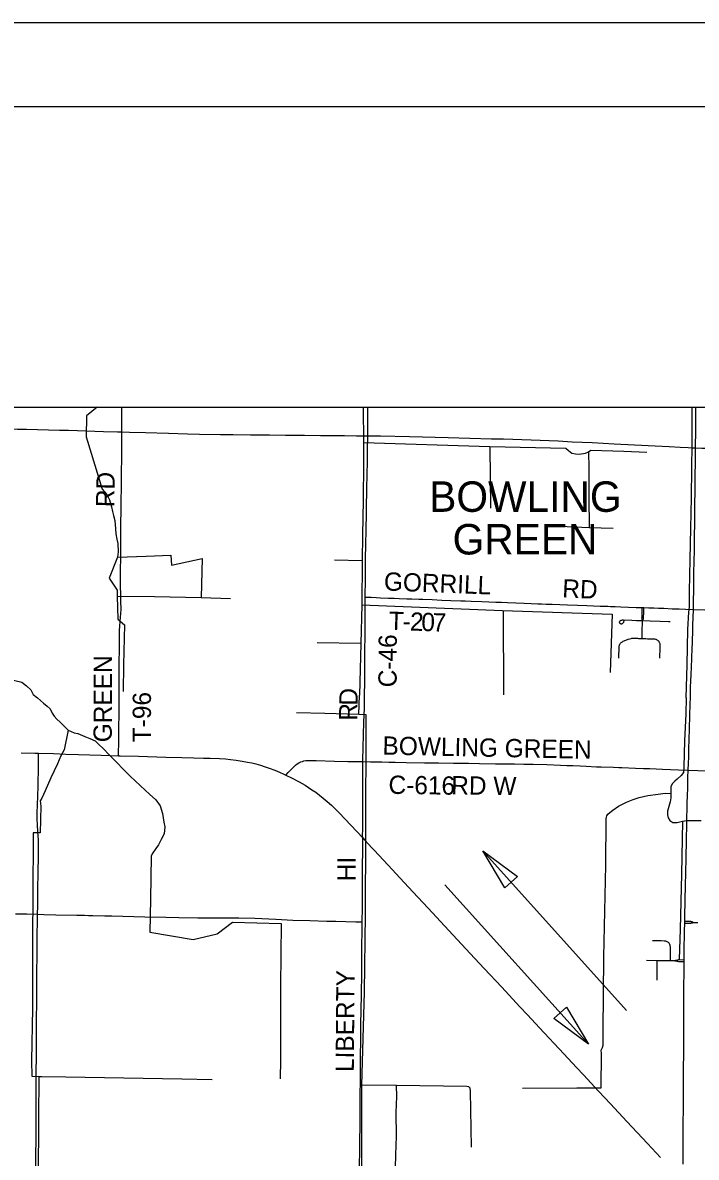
# Model space of a CAD drawing. Extents: x 0 to 680, y 0 to 834.
# Drawn here: x 187.9 to 268.3, y 304.5 to 440 of the extents above; entities that cross this region are included whole.
import ezdxf

# ---------------------------------------------------------------- set-up
doc = ezdxf.new("R2010")
doc.units = 0
for name, color, linetype in [('GM_X_City_Street', 7, 'Continuous'), ('GM_X_Corporation_Text', 7, 'Continuous'), ('GM_X_County_Road', 7, 'Continuous'), ('GM_X_County_Road_Text', 7, 'Continuous'), ('GM_X_Interstate_Route', 7, 'Continuous'), ('GM_X_Minor_River', 7, 'Continuous'), ('GM_X_Township_Road', 7, 'Continuous'), ('GM_X_Township_Road_Text', 7, 'Continuous'), ('GM_X_US_Route', 7, 'Continuous'), ('SH_Border', 7, 'Continuous'), ('SH_Cut_Line', 7, 'Continuous'), ('SH_Text', 7, 'Continuous')]:
    doc.layers.add(name, color=color, linetype=linetype)

msp = doc.modelspace()

# ---------------------------------------------------------------- linework, layer by layer
at = {"layer": 'GM_X_City_Street'}
for points in [[(261.93, 368.6), (261.87, 368.78), (261.86, 368.83), (261.85, 368.91), (261.86, 369.03), (261.86, 369.27), (261.89, 370.11), (261.9, 370.16)], [(261.93, 368.6), (262, 368.75), (262.03, 368.84), (262.05, 368.94), (262.05, 369.15), (262.06, 369.42), (262.08, 370.15)], [(259.73, 368.66), (259.69, 368.53), (259.65, 368.44), (259.63, 368.38), (259.6, 368.33), (259.57, 368.29), (259.54, 368.25), (259.5, 368.22), (259.46, 368.2), (259.41, 368.19), (259.37, 368.19), (259.32, 368.2), (259.28, 368.22), (259.24, 368.25), (259.21, 368.29), (259.19, 368.33), (259.17, 368.38), (259.17, 368.42), (259.18, 368.47), (259.19, 368.52), (259.23, 368.57), (259.27, 368.61), (259.31, 368.63), (259.35, 368.65), (259.4, 368.66), (259.45, 368.67), (259.52, 368.68), (259.64, 368.68), (260.64, 368.65), (261.21, 368.63), (261.83, 368.61), (261.93, 368.6), (262.83, 368.58), (264.02, 368.53), (265, 368.5), (265.21, 368.5)], [(261.85, 366.47), (261.86, 366.5), (261.88, 367.24), (261.93, 368.57), (261.93, 368.6)], [(259.07, 364.11), (259.07, 364.13), (259.09, 364.47), (259.11, 365.14), (259.11, 365.38), (259.12, 365.52), (259.14, 365.59), (259.16, 365.68), (259.2, 365.77), (259.23, 365.83), (259.27, 365.89), (259.32, 365.94), (259.37, 365.99), (259.43, 366.03), (259.51, 366.08), (259.6, 366.13), (259.73, 366.18), (260.22, 366.37), (260.4, 366.44), (260.54, 366.48), (260.64, 366.49), (260.77, 366.5), (260.89, 366.5), (261.32, 366.49), (261.42, 366.48), (261.85, 366.47), (262.09, 366.46), (262.13, 366.46), (262.23, 366.46), (262.3, 366.45), (262.49, 366.44), (263.02, 366.43), (263.23, 366.42), (263.35, 366.41), (263.45, 366.39), (263.51, 366.37), (263.58, 366.34), (263.64, 366.31), (263.7, 366.27), (263.76, 366.22), (263.81, 366.17), (263.85, 366.12), (263.89, 366.06), (263.92, 365.99), (263.95, 365.93), (263.97, 365.86), (263.98, 365.76), (263.99, 365.67), (263.99, 365.52), (263.98, 365.19), (263.95, 364.33), (263.94, 364.12)], [(266.96, 332.71), (267.09, 332.71), (267.57, 332.7), (267.64, 332.7), (267.72, 332.69), (267.79, 332.67), (267.87, 332.62), (267.93, 332.57)], [(266.96, 332.48), (267.08, 332.48), (267.57, 332.48), (267.67, 332.49), (267.74, 332.5), (267.8, 332.51), (267.87, 332.53), (267.93, 332.57)], [(267.93, 332.57), (268.02, 332.57), (268.5, 332.57)], [(265.26, 328.02), (265.26, 328.23), (265.25, 328.97), (265.26, 329.28), (265.25, 329.5), (265.25, 329.63), (265.23, 329.74), (265.22, 329.81), (265.18, 329.92), (265.14, 330.01), (265.08, 330.08), (265.01, 330.15), (264.94, 330.21), (264.86, 330.26), (264.79, 330.29), (264.71, 330.32), (264.65, 330.33), (264.58, 330.34), (264.49, 330.34), (264.15, 330.35), (263.1, 330.35)], [(262.4, 328.04), (263.65, 328.03), (263.96, 328.03), (265.26, 328.02), (265.3, 328.02), (265.54, 328.02)], [(263.65, 325.66), (263.65, 326.52), (263.65, 327.18), (263.65, 327.84), (263.65, 328.03)], [(265.54, 328.02), (266.14, 328.11), (266.23, 328.12), (266.29, 328.12), (266.86, 328.11), (266.89, 328.11)], [(265.54, 328.02), (265.99, 327.94), (266.13, 327.92), (266.21, 327.91), (266.28, 327.91), (266.52, 327.9), (266.86, 327.9), (266.88, 327.9)]]:
    msp.add_lwpolyline(points, dxfattribs=at)
at = {"layer": 'GM_X_County_Road'}
for points in [[(229.12, 390.4), (229.12, 390.66), (229.12, 393.31), (229.13, 394.07)], [(171.09, 391.7), (172.88, 391.68), (176.1, 391.64), (179.68, 391.58), (181.59, 391.55), (183.26, 391.53), (184.21, 391.51), (187.31, 391.45), (188.39, 391.45), (192.33, 391.36), (193.4, 391.33), (194.47, 391.3), (197.57, 391.2), (199.25, 391.15), (199.76, 391.14)], [(199.76, 391.14), (200.68, 391.11), (202.59, 391.06), (205.33, 390.97), (207.59, 390.91), (209.03, 390.88), (211.53, 390.83), (213.05, 390.81), (215.11, 390.78), (217.38, 390.77), (219.29, 390.75), (220.48, 390.74), (221.56, 390.73), (223.46, 390.72), (224.54, 390.71), (226.33, 390.69), (227.76, 390.67), (228.59, 390.65), (229.12, 390.66)], [(228.81, 371.15), (228.81, 371.41), (228.84, 373.54), (228.86, 375.45), (228.9, 378.2), (228.91, 378.91), (228.96, 381.89), (229.01, 384.4), (229.07, 387.62), (229.09, 389.41), (229.11, 390.36), (229.12, 390.4)], [(229.12, 390.66), (229.19, 390.66), (229.67, 390.67), (230.62, 390.66), (234.08, 390.58), (238.73, 390.45), (243.87, 390.32), (245.3, 390.29), (248.64, 390.19), (251.86, 390.06), (253.53, 389.96), (255.91, 389.85), (258.53, 389.71)], [(258.53, 389.71), (262.59, 389.52), (265.09, 389.38), (266.4, 389.31), (267.35, 389.27), (267.77, 389.25), (268.25, 389.23)], [(268.25, 389.23), (269.01, 389.21), (269.85, 389.2), (271.64, 389.18), (273.43, 389.14), (276.17, 389.09), (279.63, 389.03), (281.88, 388.98)], [(228.74, 359.83), (228.75, 361.14), (228.75, 362.69), (228.77, 363.76), (228.77, 364.83), (228.79, 366.98), (228.79, 367.7), (228.79, 368.17), (228.8, 370.08), (228.81, 371.15)], [(228.54, 351.48), (228.54, 351.76), (228.54, 351.95), (228.66, 356.48), (228.73, 358.15), (228.73, 358.75), (228.74, 359.83)], [(219.33, 350.16), (219.6, 350.46), (219.98, 350.84), (220.28, 351.13), (220.5, 351.33), (220.69, 351.48), (220.88, 351.61), (220.98, 351.66), (221.14, 351.74), (221.31, 351.79), (221.48, 351.84), (221.71, 351.88), (221.89, 351.9), (222.18, 351.91), (222.96, 351.9), (225.16, 351.83), (226.72, 351.79), (228.27, 351.76), (228.54, 351.76)], [(228.53, 342.37), (228.53, 342.41), (228.52, 342.66), (228.5, 343), (228.51, 343.6), (228.52, 345.75), (228.53, 347.54), (228.54, 350.28), (228.54, 351.48)], [(228.54, 351.76), (229.46, 351.74), (230.81, 351.72), (231.63, 351.7), (232.38, 351.68), (233.7, 351.66), (235.9, 351.62), (237.58, 351.6), (239.37, 351.58), (241.16, 351.57), (242.47, 351.55), (244.38, 351.51), (245.81, 351.49), (246.64, 351.49), (247.75, 351.47), (248.87, 351.45), (250.51, 351.4), (252.13, 351.34)], [(252.13, 351.34), (252.87, 351.31), (253.58, 351.28), (254.47, 351.24), (255.19, 351.21), (256.44, 351.16), (256.87, 351.15), (256.96, 351.15)], [(256.96, 351.15), (258.44, 351.09), (259.1, 351.06), (259.46, 351.05), (261.07, 350.99), (262.03, 350.96), (262.78, 350.93), (264.31, 350.87), (266.21, 350.79), (267.36, 350.75)], [(267.36, 350.75), (269.66, 350.65), (269.83, 350.64), (271.33, 350.59), (273.6, 350.49), (275.21, 350.43), (276.94, 350.36), (277.07, 350.35)], [(228.45, 332.36), (228.45, 332.63), (228.46, 332.98), (228.48, 333.94), (228.47, 334.65), (228.48, 335.37), (228.49, 337.04), (228.5, 339.43), (228.51, 340.98), (228.53, 341.93), (228.53, 342.37)], [(228.18, 298.27), (228.17, 298.53), (228.17, 298.79), (228.15, 299.46), (228.14, 300.18), (228.13, 301.37), (228.15, 303.16), (228.19, 305.66), (228.22, 309.12), (228.23, 310.91), (228.25, 314.73), (228.31, 320.34), (228.35, 323.92), (228.39, 326.54), (228.42, 328.93), (228.45, 332.36)]]:
    msp.add_lwpolyline(points, dxfattribs=at)
at = {"layer": 'GM_X_Interstate_Route'}
msp.add_lwpolyline([(44.69, 394.07), (374.69, 394.07), (374.69, 64.07), (44.69, 64.07)], close=True, dxfattribs=at)
at = {"layer": 'GM_X_Minor_River'}
for points in [[(196.82, 394.07), (195.56, 393.06), (195.49, 390.53), (197.43, 384.31), (197.99, 383.68), (198.27, 383.04), (198.51, 382.17), (198.63, 381.63), (198.77, 381.14), (198.92, 380.56), (199, 379.58), (199.05, 378.96), (199.15, 378.32), (199.27, 377.79), (199.34, 376.83), (199.26, 376.17), (198.25, 373.65), (199.2, 372.23), (199.2, 371.53), (199.28, 368.77), (200.08, 368.11), (199.97, 363.31), (199.93, 360.15)], [(228.58, 394.07), (228.61, 389.87), (228.61, 387.39), (228.57, 382.94), (228.49, 378.86), (228.46, 375.73), (228.4, 370.47), (228.28, 365.86), (228.14, 359.71)], [(267.14, 359.37), (267.25, 363.31), (267.34, 367.55), (267.43, 369.59), (267.53, 370.22), (267.53, 372.09), (267.6, 375.9), (267.69, 379.66), (267.77, 383.29), (267.81, 386.79), (267.82, 389.58), (267.84, 393.6), (267.85, 394.07)], [(228.61, 389.87), (243.68, 389.4), (252.76, 389.18), (253.06, 388.9), (253.47, 388.61), (253.92, 388.5), (254.37, 388.46), (255.1, 388.58), (255.47, 388.76), (255.73, 388.96), (259.69, 388.83), (262.41, 388.71)], [(243.68, 389.4), (243.76, 382.02)], [(255.47, 388.76), (255.5, 386.75), (255.51, 383.33), (255.56, 379.73)], [(251.15, 379.9), (255.56, 379.73), (258.42, 379.66)], [(199.26, 376.17), (202.67, 376.31), (205.61, 376.43), (205.71, 375.22), (209.34, 376.03), (209.22, 371.36)], [(228.46, 375.73), (225.15, 375.82)], [(199.2, 371.53), (203.66, 371.49), (209.22, 371.36), (212.73, 371.26)], [(228.4, 370.47), (245.21, 369.82), (258.3, 369.39), (258.05, 362.39)], [(245.26, 369.79), (245.3, 359.75)], [(228.28, 365.86), (223.07, 365.93)], [(182.64, 360.38), (183.96, 360.9), (184.92, 361.23), (185.72, 361.42), (186.28, 361.51), (186.99, 361.44), (187.81, 361.24), (188.4, 360.83), (188.89, 360.32)], [(188.89, 360.32), (189.16, 359.78), (189.7, 359.38), (190.4, 358.75), (190.86, 358.37), (191.22, 358.05), (191.46, 357.55), (191.67, 357.19), (192.02, 356.82), (192.39, 356.49), (193, 355.86), (193.37, 355.53), (194.07, 355.2), (194.51, 355.12), (195.35, 354.77), (195.95, 354.51), (196.56, 354.23), (197.07, 353.77), (197.49, 353.35), (198.33, 352.51), (200.77, 350.03), (202.53, 348.36), (203.05, 347.89), (203.84, 347.19), (204.32, 346.49), (204.61, 345.55), (204.79, 344.52), (204.89, 343.98), (204.8, 343.13), (204.47, 342.46), (204.14, 341.82), (203.84, 341.4), (203.4, 340.77), (203.26, 340.48), (203.18, 335.34), (203.12, 331.39), (208.26, 330.52), (211.13, 331.19), (212.97, 332.6), (218.79, 332.45), (218.72, 324.96), (218.71, 316.16), (218.66, 313.88)], [(228.06, 357.4), (228.14, 359.71)], [(267.14, 359.37), (267.07, 357.48), (266.92, 354.25), (266.86, 351.13), (266.82, 350.46), (266.53, 350.1), (266.03, 349.65), (265.78, 349.43), (265.46, 349.11), (265.3, 348.76), (265.28, 348.41), (265.31, 347.96), (265.29, 347.43), (265.21, 346.98), (265.07, 346.41), (264.91, 345.83), (264.9, 345.42), (264.97, 345.07), (265.18, 344.73), (265.52, 344.51), (266.06, 344.48), (266.7, 344.64), (267.17, 344.73), (267.97, 344.75), (268.93, 344.73)], [(228.96, 299.35), (228.86, 300.64), (228.73, 301.09), (228.6, 301.34), (228.46, 301.73), (228.42, 302.53), (228.42, 313.14), (228.74, 324.28), (228.83, 333.5), (228.87, 343.1), (228.89, 347.61), (228.91, 352.15), (228.94, 355.48), (228.93, 357.36), (228.06, 357.4), (223.98, 357.49), (220.6, 357.57)], [(193.37, 355.53), (192.89, 353.17), (192.49, 352.47), (192.08, 351.48), (191.27, 349.84), (190.63, 348.29), (190.2, 347.39), (190.01, 347.08), (190.11, 346.44), (190.01, 343.27), (189.18, 343.26), (189.12, 335.47), (189.09, 331.1), (189.09, 326.75), (189.09, 322.33), (188.99, 316.03), (189.01, 314.2), (189.84, 314.17), (190.2, 314.15), (193.06, 314.12), (200.02, 314), (206.93, 313.89), (210.54, 313.79)], [(247.59, 312.76), (254.07, 312.82), (256.96, 312.82), (257, 316.89), (256.99, 317.3), (257.13, 317.61), (257.22, 317.9), (257.2, 319.61), (257.31, 328.4), (257.53, 339.39), (257.59, 344.92), (257.61, 345.12), (257.67, 345.28), (257.76, 345.47), (258, 345.7), (258.36, 345.98), (259.04, 346.44), (260, 346.94), (260.78, 347.25), (261.51, 347.46), (262.53, 347.73), (263.77, 347.87), (264.63, 348), (265.31, 347.96)], [(266.7, 344.64), (266.55, 338.34), (266.41, 331.74), (266.3, 328.13)], [(189.84, 314.17), (189.8, 309.14), (189.79, 302.09), (189.81, 295.76), (189.8, 292.27)], [(241.51, 305.71), (241.37, 312.4), (241.34, 312.78), (241.18, 312.93), (240.95, 312.96), (232.56, 313.07), (228.42, 313.14)], [(232.41, 303.27), (232.47, 304.8), (232.54, 307.03), (232.5, 309.87), (232.58, 311.77), (232.56, 313.07)]]:
    msp.add_lwpolyline(points, dxfattribs=at)
at = {"layer": 'GM_X_Township_Road'}
for points in [[(199.76, 391.14), (199.76, 391.71), (199.77, 393.86), (199.77, 394.07)], [(268.25, 389.23), (268.25, 389.83), (268.26, 390.74), (268.27, 392.27), (268.29, 393.72), (268.29, 394.07)], [(199.46, 362.35), (199.46, 363.43), (199.47, 365.34), (199.49, 367.37), (199.51, 367.97), (199.55, 368.44), (199.62, 369.04), (199.65, 369.39), (199.67, 369.99), (199.66, 370.83), (199.63, 371.78), (199.6, 372.62), (199.59, 373.45), (199.6, 374.53), (199.63, 376.2), (199.65, 378.11), (199.65, 379.54), (199.66, 380.26), (199.67, 381.69), (199.7, 383), (199.72, 384.43), (199.74, 386.46), (199.76, 387.89), (199.75, 388.61), (199.76, 389.92), (199.77, 390.99), (199.76, 391.14)], [(267.98, 369.91), (267.99, 370.74), (268.02, 372.43), (268.04, 373.63), (268.05, 374.34), (268.07, 375.63), (268.1, 377.06), (268.13, 379.12), (268.14, 379.81), (268.15, 381.1), (268.16, 381.91), (268.17, 382.48), (268.17, 382.89), (268.18, 383.65), (268.18, 384.25), (268.19, 384.89), (268.21, 386.18), (268.22, 387.23), (268.23, 388), (268.24, 388.47), (268.25, 389.23)], [(228.81, 371.41), (229.03, 371.4), (229.53, 371.39), (230.13, 371.36), (230.65, 371.33), (231.61, 371.3), (232.25, 371.28), (232.85, 371.26), (233.8, 371.22), (234.37, 371.2), (235.21, 371.16), (235.68, 371.15), (236.8, 371.11), (237.97, 371.06), (239.02, 371.02), (240.24, 370.97), (240.74, 370.96), (241.46, 370.93), (242.72, 370.88), (244.41, 370.81), (245.08, 370.79), (245.8, 370.77), (247.8, 370.69), (248.63, 370.66), (249.42, 370.62), (249.85, 370.6), (250.42, 370.58), (251.07, 370.56)], [(251.07, 370.56), (251.14, 370.55), (252.97, 370.48), (254.17, 370.43), (255.28, 370.4), (256.87, 370.34), (257.77, 370.31), (258.1, 370.29)], [(258.1, 370.29), (258.65, 370.27), (259.31, 370.25), (260.24, 370.21), (261.17, 370.18), (261.9, 370.16)], [(261.9, 370.16), (261.94, 370.16), (262.08, 370.15)], [(262.08, 370.15), (262.65, 370.14), (263.01, 370.13), (263.27, 370.12), (263.84, 370.09), (264.44, 370.07), (265.46, 370.02), (266.3, 369.99), (267.06, 369.96), (267.98, 369.91)], [(267.36, 350.75), (267.4, 351.59), (267.43, 352.31), (267.45, 353.26), (267.52, 355.62), (267.54, 356.17), (267.57, 356.79), (267.58, 357.34), (267.61, 358.56), (267.64, 359.51), (267.64, 359.99), (267.66, 360.58), (267.7, 361.44), (267.73, 362.13), (267.77, 363.09), (267.8, 364.02), (267.81, 364.37), (267.83, 365.07), (267.87, 366.16), (267.9, 367.38), (267.92, 368.09), (267.95, 368.93), (267.98, 369.91)], [(267.98, 369.91), (269.34, 369.87), (269.49, 369.87), (270.77, 369.85), (271.88, 369.83), (271.98, 369.83), (272.08, 369.83), (272.72, 369.82), (273.42, 369.81), (273.61, 369.81), (274.65, 369.78), (275.78, 369.77), (276.4, 369.75)], [(199.37, 352.47), (199.38, 352.81), (199.4, 354), (199.42, 355.67), (199.43, 357.58), (199.45, 359.25), (199.46, 361.88), (199.46, 362.35)], [(189.71, 333.55), (189.72, 334.56), (189.75, 336.7), (189.77, 338.37), (189.8, 340.64), (189.82, 342.06), (189.81, 342.54), (189.79, 342.78), (189.72, 343.49), (189.69, 344.08), (189.66, 345.04), (189.67, 345.75), (189.69, 346.47), (189.75, 347.77), (189.77, 348.73), (189.81, 351.35), (189.82, 352.18), (189.82, 352.54), (189.82, 352.76)], [(266.96, 332.48), (266.96, 332.71), (266.98, 333.3), (267.06, 337.05), (267.09, 338.41), (267.13, 340.32), (267.14, 341.17), (267.15, 341.46), (267.17, 342.61), (267.18, 343.21), (267.19, 343.44), (267.2, 344.11), (267.22, 345.23), (267.24, 345.97), (267.26, 346.88), (267.28, 347.64), (267.31, 348.67), (267.33, 349.86), (267.36, 350.75)], [(187.05, 333.58), (188.43, 333.58), (189.71, 333.55)], [(189.49, 302.88), (189.51, 304.79), (189.52, 306.59), (189.52, 308.02), (189.52, 309.93), (189.52, 311.84), (189.54, 313.76), (189.55, 314.83), (189.56, 316.38), (189.57, 317.7), (189.57, 318.89), (189.58, 320.69), (189.61, 323.31), (189.63, 325.35), (189.67, 329.89), (189.66, 330.96), (189.67, 331.57), (189.69, 332.19), (189.69, 332.59), (189.71, 333.35), (189.71, 333.55)], [(189.71, 333.55), (190.47, 333.52), (191.89, 333.48), (194.4, 333.44), (195.29, 333.41), (195.78, 333.4), (196.29, 333.39), (197.72, 333.35), (198.56, 333.33), (199.87, 333.3), (201.19, 333.27), (202.5, 333.23), (205.01, 333.19), (206.56, 333.16), (208.83, 333.12), (209.66, 333.11), (210.98, 333.11), (212.53, 333.09), (213.72, 333.09), (215.63, 333.05), (218.14, 332.96), (220.17, 332.85), (222.2, 332.8), (224.23, 332.73), (225.3, 332.71), (227.69, 332.63), (228.17, 332.62), (228.29, 332.63), (228.45, 332.63)], [(266.88, 327.9), (266.89, 328.11), (266.89, 328.61), (266.9, 329.23), (266.94, 331.3), (266.94, 331.54), (266.96, 332.48)], [(266.88, 327.26), (266.88, 327.29), (266.88, 327.9)], [(266.85, 321.71), (266.85, 323.14), (266.85, 324.07), (266.85, 325), (266.87, 326.5), (266.87, 326.81), (266.88, 327.26)], [(266.83, 316.9), (266.84, 319.74), (266.85, 321.53), (266.85, 321.71)], [(266.81, 314.25), (266.81, 314.78), (266.82, 314.97), (266.82, 315.91), (266.83, 316.1), (266.83, 316.9)], [(266.81, 313.04), (266.81, 313.28), (266.81, 314.25)], [(266.81, 312.08), (266.81, 312.92), (266.81, 313.04)], [(266.76, 303.71), (266.76, 303.9), (266.76, 305.17), (266.78, 306.5), (266.78, 307.62), (266.78, 308.43), (266.8, 310.44), (266.81, 312.08)]]:
    msp.add_lwpolyline(points, dxfattribs=at)
at = {"layer": 'GM_X_US_Route'}
for points in [[(187.76, 352.82), (189.38, 352.77), (189.82, 352.76), (191.6, 352.72), (193.08, 352.67), (194.59, 352.61), (197.31, 352.53), (199.37, 352.47), (199.57, 352.46), (201.77, 352.42), (205.01, 352.31), (206.92, 352.25), (208.35, 352.21), (209.51, 352.18)], [(209.51, 352.18), (210.31, 352.16), (211.43, 352.12), (212.13, 352.08), (212.72, 352.02), (213.41, 351.93), (214.14, 351.82), (214.78, 351.7), (215.27, 351.6), (215.76, 351.48), (216.31, 351.32), (216.86, 351.16), (217.36, 350.98), (218.02, 350.73), (218.6, 350.49), (219.1, 350.27)], [(219.1, 350.27), (219.17, 350.24), (219.33, 350.16), (220.03, 349.82), (220.91, 349.35), (221.65, 348.94), (222.45, 348.41), (222.91, 348.1), (223.35, 347.77), (223.81, 347.4), (224.27, 347.01), (224.79, 346.55), (225.24, 346.12), (225.74, 345.61), (226.4, 344.92), (228.52, 342.66), (228.94, 342.2), (229.89, 341.2), (231.55, 339.4), (232.99, 337.85), (234.5, 336.22), (236.31, 334.28), (238.81, 331.59), (241.35, 328.86), (243.03, 327.07), (245.11, 324.83), (247.27, 322.5), (248.18, 321.52), (249.62, 319.99), (252.53, 316.86), (254.05, 315.24), (254.88, 314.35), (256.65, 312.42), (258.09, 310.88), (260.05, 308.79), (262.5, 306.15), (264.07, 304.48)]]:
    msp.add_lwpolyline(points, dxfattribs=at)
at = {"layer": 'SH_Border'}
msp.add_lwpolyline([(30, 430), (670, 430), (670, 10), (30, 10)], close=True, dxfattribs=at)
at = {"layer": 'SH_Cut_Line'}
msp.add_lwpolyline([(0, 0), (680, 0), (680, 440), (0, 440)], close=True, dxfattribs=at)
at = {"layer": 'SH_Text'}
for p, q in [((242.86, 341.11), (260, 322.05)), ((255.46, 318.01), (238.33, 337.06))]:
    msp.add_line(p, q, dxfattribs=at)
for points in [[(245.48, 336.69), (242.86, 341.11), (246.98, 338.03)], [(252.84, 322.43), (255.46, 318.01), (251.34, 321.08)]]:
    msp.add_lwpolyline(points, close=True, dxfattribs=at)

# ---------------------------------------------------------------- texts
at = {"layer": 'GM_X_Corporation_Text'}
for s, p in [('BOWLING', (236.45, 381.59)), ('GREEN', (239.24, 376.5))]:
    msp.add_text(s, height=3.636, rotation=0, dxfattribs=at).set_placement(p)
at = {"layer": 'GM_X_County_Road_Text'}
for s, height, rotation, p in [('C-46', 2.182, 89.6646, (232.56, 360.63)), ('D', 2.18, 88.9508, (227.89, 358.43)), ('R', 2.18, 89.4653, (227.87, 356.64)), ('BOWLING GREEN', 2.1818, 358.8439, (230.86, 352.6)), ('C-616', 2.182, 359.1792, (231.58, 347.92)), ('RD W', 2.182, 359.2109, (239.07, 347.86)), ('HI', 2.182, 90, (227.68, 337.47)), ('LIBERTY', 2.182, 89.5123, (227.45, 314.69))]:
    msp.add_text(s, height=height, rotation=rotation, dxfattribs=at).set_placement(p)
at = {"layer": 'GM_X_Township_Road_Text'}
for s, height, rotation, p in [('RD', 2.182, 89.0302, (198.85, 382.13)), ('GORRILL', 2.182, 357.7853, (231.01, 372.21)), ('RD', 2.182, 357.5515, (252.3, 371.38)), ('T', 2.18, 357.9468, (231.6, 367.51)), ('2', 2.18, 357.9614, (234.13, 367.42)), ('0', 2.18, 358.0262, (235.48, 367.37)), ('7', 2.18, 358.292, (236.83, 367.32)), ('-', 2.18, 357.9387, (233.24, 367.45)), ('GREEN', 2.182, 89.7949, (198.56, 354.07)), ('T-96', 2.182, 90, (203.24, 354.08))]:
    msp.add_text(s, height=height, rotation=rotation, dxfattribs=at).set_placement(p)

doc.saveas('drawing.dxf')
